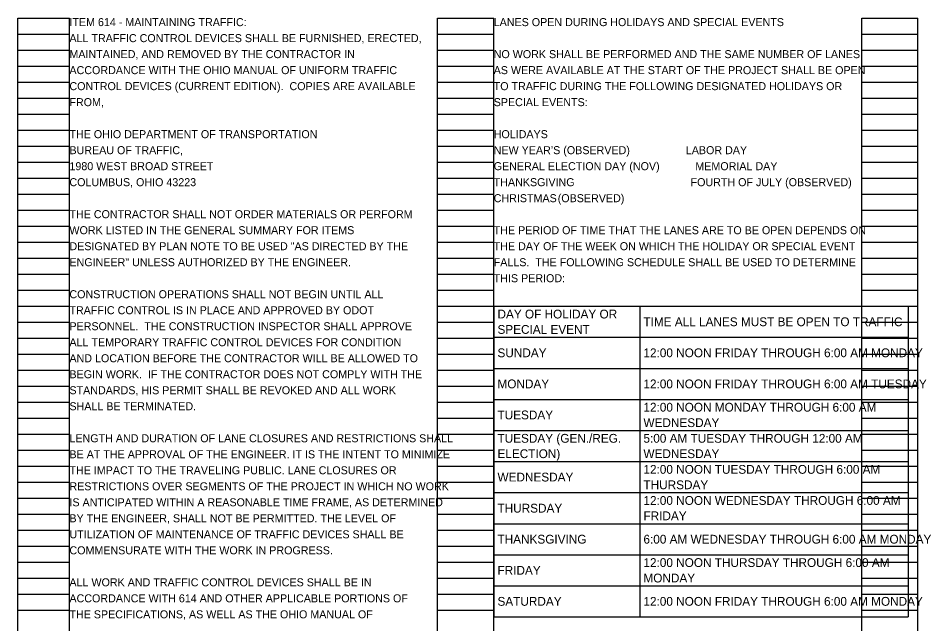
# Model space of a CAD drawing. Extents: x 51924.2 to 51956.2, y 31431.6 to 31530.7.
# Drawn here: x 51925.71 to 51941.45, y 31520.1 to 31530.69 of the extents above; entities that cross this region are included whole.
import ezdxf

# ---------------------------------------------------------------- set-up
doc = ezdxf.new("R2010")
doc.units = 0
doc.layers.add('SH_Data', color=7, linetype='Continuous')
doc.layers.add('SH_Text', color=7, linetype='Continuous')

msp = doc.modelspace()

# ---------------------------------------------------------------- linework, layer by layer
at = {"layer": 'SH_Data'}
for p, q in [((51925.708, 31510.524), (51925.708, 31530.684)), ((51925.708, 31530.684), (51926.608, 31530.684)), ((51926.608, 31510.524), (51926.608, 31530.684)), ((51933.048, 31510.524), (51933.048, 31530.684)), ((51933.048, 31530.684), (51934.028, 31530.684)), ((51934.028, 31510.524), (51934.028, 31530.684)), ((51940.468, 31510.524), (51940.468, 31530.684)), ((51940.468, 31530.684), (51941.448, 31530.684)), ((51941.448, 31510.524), (51941.448, 31530.684)), ((51925.708, 31530.404), (51926.608, 31530.404)), ((51933.048, 31530.404), (51934.028, 31530.404)), ((51940.468, 31530.404), (51941.448, 31530.404)), ((51925.708, 31530.124), (51926.608, 31530.124)), ((51933.048, 31530.124), (51934.028, 31530.124)), ((51940.468, 31530.124), (51941.448, 31530.124)), ((51925.708, 31529.844), (51926.608, 31529.844)), ((51933.048, 31529.844), (51934.028, 31529.844)), ((51940.468, 31529.844), (51941.448, 31529.844)), ((51925.708, 31529.564), (51926.608, 31529.564)), ((51933.048, 31529.564), (51934.028, 31529.564)), ((51940.468, 31529.564), (51941.448, 31529.564)), ((51925.708, 31529.284), (51926.608, 31529.284)), ((51933.048, 31529.284), (51934.028, 31529.284)), ((51940.468, 31529.284), (51941.448, 31529.284)), ((51925.708, 31529.004), (51926.608, 31529.004)), ((51933.048, 31529.004), (51934.028, 31529.004)), ((51940.468, 31529.004), (51941.448, 31529.004)), ((51925.708, 31528.724), (51926.608, 31528.724)), ((51933.048, 31528.724), (51934.028, 31528.724)), ((51940.468, 31528.724), (51941.448, 31528.724)), ((51925.708, 31528.444), (51926.608, 31528.444)), ((51933.048, 31528.444), (51934.028, 31528.444)), ((51940.468, 31528.444), (51941.448, 31528.444)), ((51925.708, 31528.164), (51926.608, 31528.164)), ((51933.048, 31528.164), (51934.028, 31528.164)), ((51940.468, 31528.164), (51941.448, 31528.164)), ((51925.708, 31527.884), (51926.608, 31527.884)), ((51933.048, 31527.884), (51934.028, 31527.884)), ((51940.468, 31527.884), (51941.448, 31527.884)), ((51925.708, 31527.604), (51926.608, 31527.604)), ((51933.048, 31527.604), (51934.028, 31527.604)), ((51940.468, 31527.604), (51941.448, 31527.604)), ((51925.708, 31527.324), (51926.608, 31527.324)), ((51933.048, 31527.324), (51934.028, 31527.324)), ((51940.468, 31527.324), (51941.448, 31527.324)), ((51925.708, 31527.044), (51926.608, 31527.044)), ((51933.048, 31527.044), (51934.028, 31527.044)), ((51940.468, 31527.044), (51941.448, 31527.044)), ((51925.708, 31526.764), (51926.608, 31526.764)), ((51933.048, 31526.764), (51934.028, 31526.764)), ((51940.468, 31526.764), (51941.448, 31526.764)), ((51925.708, 31526.484), (51926.608, 31526.484)), ((51933.048, 31526.484), (51934.028, 31526.484)), ((51940.468, 31526.484), (51941.448, 31526.484)), ((51925.708, 31526.204), (51926.608, 31526.204)), ((51933.048, 31526.204), (51934.028, 31526.204)), ((51940.468, 31526.204), (51941.448, 31526.204)), ((51925.708, 31525.924), (51926.608, 31525.924)), ((51933.048, 31525.924), (51934.028, 31525.924)), ((51940.468, 31525.924), (51941.448, 31525.924)), ((51925.708, 31525.644), (51926.608, 31525.644)), ((51933.048, 31525.644), (51934.028, 31525.644)), ((51934.028, 31525.644), (51941.276, 31525.644)), ((51934.028, 31525.644), (51934.028, 31520.209)), ((51936.581, 31525.644), (51936.581, 31520.209)), ((51940.468, 31525.644), (51941.448, 31525.644)), ((51941.276, 31525.644), (51941.276, 31520.209)), ((51925.708, 31525.364), (51926.608, 31525.364)), ((51933.048, 31525.364), (51934.028, 31525.364)), ((51940.468, 31525.364), (51941.448, 31525.364)), ((51925.708, 31525.084), (51926.608, 31525.084)), ((51933.048, 31525.084), (51934.028, 31525.084)), ((51934.028, 31525.101), (51941.276, 31525.101)), ((51940.468, 31525.084), (51941.448, 31525.084)), ((51925.708, 31524.804), (51926.608, 31524.804)), ((51933.048, 31524.804), (51934.028, 31524.804)), ((51940.468, 31524.804), (51941.448, 31524.804)), ((51925.708, 31524.524), (51926.608, 31524.524)), ((51933.048, 31524.524), (51934.028, 31524.524)), ((51934.028, 31524.557), (51941.276, 31524.557)), ((51940.468, 31524.524), (51941.448, 31524.524)), ((51925.708, 31524.244), (51926.608, 31524.244)), ((51933.048, 31524.244), (51934.028, 31524.244)), ((51940.468, 31524.244), (51941.448, 31524.244)), ((51934.028, 31524.014), (51941.276, 31524.014)), ((51925.708, 31523.964), (51926.608, 31523.964)), ((51933.048, 31523.964), (51934.028, 31523.964)), ((51940.468, 31523.964), (51941.448, 31523.964)), ((51925.708, 31523.684), (51926.608, 31523.684)), ((51933.048, 31523.684), (51934.028, 31523.684)), ((51940.468, 31523.684), (51941.448, 31523.684)), ((51925.708, 31523.404), (51926.608, 31523.404)), ((51933.048, 31523.404), (51934.028, 31523.404)), ((51934.028, 31523.47), (51941.276, 31523.47)), ((51940.468, 31523.404), (51941.448, 31523.404)), ((51925.708, 31523.124), (51926.608, 31523.124)), ((51933.048, 31523.124), (51934.028, 31523.124)), ((51940.468, 31523.124), (51941.448, 31523.124)), ((51934.028, 31522.927), (51941.276, 31522.927)), ((51925.708, 31522.844), (51926.608, 31522.844)), ((51933.048, 31522.844), (51934.028, 31522.844)), ((51940.468, 31522.844), (51941.448, 31522.844)), ((51925.708, 31522.564), (51926.608, 31522.564)), ((51933.048, 31522.564), (51934.028, 31522.564)), ((51940.468, 31522.564), (51941.448, 31522.564)), ((51925.708, 31522.284), (51926.608, 31522.284)), ((51933.048, 31522.284), (51934.028, 31522.284)), ((51934.028, 31522.383), (51941.276, 31522.383)), ((51940.468, 31522.284), (51941.448, 31522.284)), ((51925.708, 31522.004), (51926.608, 31522.004)), ((51933.048, 31522.004), (51934.028, 31522.004)), ((51940.468, 31522.004), (51941.448, 31522.004)), ((51934.028, 31521.84), (51941.276, 31521.84)), ((51925.708, 31521.724), (51926.608, 31521.724)), ((51933.048, 31521.724), (51934.028, 31521.724)), ((51940.468, 31521.724), (51941.448, 31521.724)), ((51925.708, 31521.444), (51926.608, 31521.444)), ((51933.048, 31521.444), (51934.028, 31521.444)), ((51934.028, 31521.296), (51941.276, 31521.296)), ((51940.468, 31521.444), (51941.448, 31521.444)), ((51925.708, 31521.164), (51926.608, 31521.164)), ((51933.048, 31521.164), (51934.028, 31521.164)), ((51940.468, 31521.164), (51941.448, 31521.164)), ((51925.708, 31520.884), (51926.608, 31520.884)), ((51933.048, 31520.884), (51934.028, 31520.884)), ((51940.468, 31520.884), (51941.448, 31520.884)), ((51934.028, 31520.752), (51941.276, 31520.752)), ((51925.708, 31520.604), (51926.608, 31520.604)), ((51933.048, 31520.604), (51934.028, 31520.604)), ((51940.468, 31520.604), (51941.448, 31520.604)), ((51925.708, 31520.324), (51926.608, 31520.324)), ((51933.048, 31520.324), (51934.028, 31520.324)), ((51934.028, 31520.209), (51941.276, 31520.209)), ((51940.468, 31520.324), (51941.448, 31520.324))]:
    msp.add_line(p, q, dxfattribs=at)

# ---------------------------------------------------------------- texts
for s, height, p in [('LANES OPEN DURING HOLIDAYS AND SPECIAL EVENTS', 0.14, (51934.028, 31530.544)), ('NO WORK SHALL BE PERFORMED AND THE SAME NUMBER OF LANES ', 0.14, (51934.028, 31529.984)), ('AS WERE AVAILABLE AT THE START OF THE PROJECT SHALL BE OPEN ', 0.14, (51934.028, 31529.704)), ('TO TRAFFIC DURING THE FOLLOWING DESIGNATED HOLIDAYS OR ', 0.14, (51934.028, 31529.424)), ('SPECIAL EVENTS:', 0.14, (51934.028, 31529.144)), ('HOLIDAYS', 0.14, (51934.028, 31528.584)), ('NEW YEAR’S (OBSERVED)', 0.14, (51934.028, 31528.304)), ('LABOR DAY', 0.14, (51937.388, 31528.304)), ('GENERAL ELECTION DAY (NOV)            MEMORIAL DAY ', 0.14, (51934.028, 31528.024)), ('THANKSGIVING                                       FOURTH OF JULY\xa0(OBSERVED)', 0.14, (51934.028, 31527.744)), ('CHRISTMAS', 0.14, (51934.028, 31527.464)), ('(OBSERVED)', 0.14, (51935.148, 31527.464)), ('THE PERIOD OF TIME THAT THE LANES ARE TO BE OPEN DEPENDS ON ', 0.14, (51934.028, 31526.904)), ('THE DAY OF THE WEEK ON WHICH THE HOLIDAY OR SPECIAL EVENT ', 0.14, (51934.028, 31526.624)), ('FALLS.  THE FOLLOWING SCHEDULE SHALL BE USED TO DETERMINE ', 0.14, (51934.028, 31526.344)), ('THIS PERIOD:', 0.14, (51934.028, 31526.064)), ('DAY OF HOLIDAY OR ', 0.154, (51934.094, 31525.43)), ('TIME ALL LANES MUST BE OPEN TO TRAFFIC', 0.154, (51936.647, 31525.295)), ('SPECIAL EVENT', 0.154, (51934.094, 31525.161)), ('SUNDAY', 0.154, (51934.094, 31524.752)), ('12:00 NOON FRIDAY THROUGH 6:00 AM MONDAY', 0.154, (51936.647, 31524.752)), ('MONDAY', 0.154, (51934.094, 31524.208)), ('12:00 NOON FRIDAY THROUGH 6:00 AM TUESDAY', 0.154, (51936.647, 31524.208)), ('TUESDAY', 0.154, (51934.094, 31523.665)), ('12:00 NOON MONDAY THROUGH 6:00 AM ', 0.154, (51936.647, 31523.8)), ('WEDNESDAY', 0.154, (51936.647, 31523.53)), ('TUESDAY (GEN./REG. ', 0.154, (51934.094, 31523.256)), ('5:00 AM TUESDAY THROUGH 12:00 AM ', 0.154, (51936.647, 31523.256)), ('ELECTION)', 0.154, (51934.094, 31522.987)), ('WEDNESDAY', 0.154, (51936.647, 31522.987)), ('12:00 NOON TUESDAY THROUGH 6:00 AM ', 0.154, (51936.647, 31522.713)), ('WEDNESDAY', 0.154, (51934.094, 31522.578)), ('THURSDAY', 0.154, (51936.647, 31522.443)), ('12:00 NOON WEDNESDAY THROUGH 6:00 AM ', 0.154, (51936.647, 31522.169)), ('THURSDAY', 0.154, (51934.094, 31522.034)), ('FRIDAY', 0.154, (51936.647, 31521.9)), ('THANKSGIVING', 0.154, (51934.094, 31521.491)), ('6:00 AM WEDNESDAY THROUGH 6:00 AM MONDAY', 0.154, (51936.647, 31521.491)), ('12:00 NOON THURSDAY THROUGH 6:00 AM ', 0.154, (51936.647, 31521.082)), ('FRIDAY', 0.154, (51934.094, 31520.947)), ('MONDAY', 0.154, (51936.647, 31520.812)), ('SATURDAY', 0.154, (51934.094, 31520.404)), ('12:00 NOON FRIDAY THROUGH 6:00 AM MONDAY', 0.154, (51936.647, 31520.404))]:
    msp.add_text(s, height=height, dxfattribs=at).set_placement(p)
at = {"layer": 'SH_Text'}
for s, p in [('ITEM 614 - MAINTAINING TRAFFIC:', (51926.608, 31530.544)), ('ALL TRAFFIC CONTROL DEVICES SHALL BE FURNISHED, ERECTED, ', (51926.608, 31530.264)), ('MAINTAINED, AND REMOVED BY THE CONTRACTOR IN ', (51926.608, 31529.984)), ('ACCORDANCE WITH THE OHIO MANUAL OF UNIFORM TRAFFIC ', (51926.608, 31529.704)), ('CONTROL DEVICES (CURRENT EDITION).  COPIES ARE AVAILABLE ', (51926.608, 31529.424)), ('FROM,', (51926.608, 31529.144)), ('THE OHIO DEPARTMENT OF TRANSPORTATION', (51926.608, 31528.584)), ('BUREAU OF TRAFFIC,', (51926.608, 31528.304)), ('1980 WEST BROAD STREET', (51926.608, 31528.024)), ('COLUMBUS, OHIO 43223', (51926.608, 31527.744)), ('THE CONTRACTOR SHALL NOT ORDER MATERIALS OR PERFORM ', (51926.608, 31527.184)), ('WORK LISTED IN THE GENERAL SUMMARY FOR ITEMS ', (51926.608, 31526.904)), ('DESIGNATED BY PLAN NOTE TO BE USED "AS DIRECTED BY THE ', (51926.608, 31526.624)), ('ENGINEER" UNLESS AUTHORIZED BY THE ENGINEER.', (51926.608, 31526.344)), ('CONSTRUCTION OPERATIONS SHALL NOT BEGIN UNTIL ALL ', (51926.608, 31525.784)), ('TRAFFIC CONTROL IS IN PLACE AND APPROVED BY ODOT ', (51926.608, 31525.504)), ('PERSONNEL.  THE CONSTRUCTION INSPECTOR SHALL APPROVE ', (51926.608, 31525.224)), ('ALL TEMPORARY TRAFFIC CONTROL DEVICES FOR CONDITION ', (51926.608, 31524.944)), ('AND LOCATION BEFORE THE CONTRACTOR WILL BE ALLOWED TO ', (51926.608, 31524.664)), ('BEGIN WORK.  IF THE CONTRACTOR DOES NOT COMPLY WITH THE ', (51926.608, 31524.384)), ('STANDARDS, HIS PERMIT SHALL BE REVOKED AND ALL WORK ', (51926.608, 31524.104)), ('SHALL BE TERMINATED.', (51926.608, 31523.824)), ('LENGTH AND DURATION OF LANE CLOSURES AND RESTRICTIONS SHALL ', (51926.608, 31523.264)), ('BE AT THE APPROVAL OF THE ENGINEER. IT IS THE INTENT TO MINIMIZE ', (51926.608, 31522.984)), ('THE IMPACT TO THE TRAVELING PUBLIC. LANE CLOSURES OR ', (51926.608, 31522.704)), ('RESTRICTIONS OVER SEGMENTS OF THE PROJECT IN WHICH NO WORK ', (51926.608, 31522.424)), ('IS ANTICIPATED WITHIN A REASONABLE TIME FRAME, AS DETERMINED ', (51926.608, 31522.144)), ('BY THE ENGINEER, SHALL NOT BE PERMITTED. THE LEVEL OF ', (51926.608, 31521.864)), ('UTILIZATION OF MAINTENANCE OF TRAFFIC DEVICES SHALL BE ', (51926.608, 31521.584)), ('COMMENSURATE WITH THE WORK IN PROGRESS.', (51926.608, 31521.304)), ('ALL WORK AND TRAFFIC CONTROL DEVICES SHALL BE IN ', (51926.608, 31520.744)), ('ACCORDANCE WITH 614 AND OTHER APPLICABLE PORTIONS OF ', (51926.608, 31520.464)), ('THE SPECIFICATIONS, AS WELL AS THE OHIO MANUAL OF ', (51926.608, 31520.184))]:
    msp.add_text(s, height=0.14, dxfattribs=at).set_placement(p)

doc.saveas('drawing.dxf')
